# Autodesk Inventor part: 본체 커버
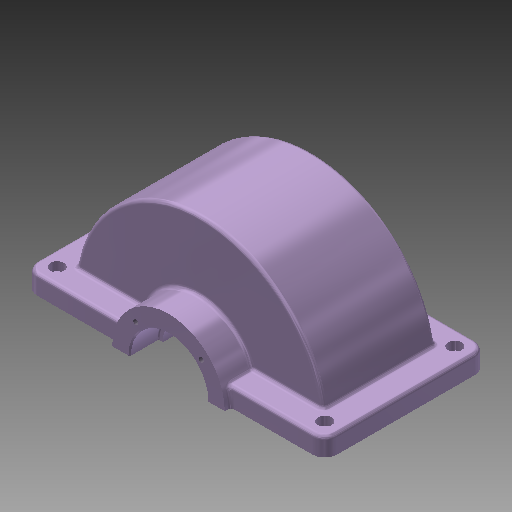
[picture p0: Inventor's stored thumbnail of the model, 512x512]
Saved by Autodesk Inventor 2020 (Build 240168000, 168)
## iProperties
Created: 2023-06
Part Number: 본체 커버
Material: 알루미늄 6061
Document SubType Name: Modeling
Designer: mdu-01
Density: 1 g/cm^3
Appearance: 알루미늄 - 평지(1)
Author: mdu-01
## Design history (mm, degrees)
sketch "스케치1"
  geometry: L1 (0, 70)-(0, -70); L2 (0, 70)-(45, 70); L3 (45, 70)-(45, 45); L4 (45, 45)-(100, 45); L5 (0, 0)-(100, 0); L6 (0, -70)-(45, -70); L7 (45, -70)-(45, -45); L8 (45, -45)-(100, -45); L9 (100, 45)-(100, -45); 1 further point
  constraints: 18 end point, 3 perpendicular, 3 symmetric about line, 2 midpoint, 2 parallel, 1 coincident, 1 vertical
  dimensions: "d0" = 140 distance of L1.start L1.end; "d1" = 90 diameter of L3 L1; "d2" = 90 distance between parallel lines of L8 L4; "d3" = 200 diameter of L9 L1
revolve "회전1" sketch "스케치1" stored, may be unused: angle "d4" = 180 deg
sketch "스케치2"
  geometry: L1 (-10, -110)-(210, -110); L2 (220, -100)-(220, 10); L3 (210, 20)-(-10, 20); L4 (-20, 10)-(-20, -100); L5 (-20, -110)-(220, 20); L6 (220, -110)-(-20, 20); A1 r 10 centre (-10, 10) between (-10, 20) and (-20, 10); A2 r 10 centre (210, 10) between (220, 10) and (210, 20); A3 r 10 centre (210, -100) between (210, -110) and (220, -100); A4 r 10 centre (-10, -100) between (-20, -100) and (-10, -110); 1 further point
  constraints: 12 end point, 8 point on circle, 8 point on line, 8 tangent, 4 centre point, 3 equal radius, 2 midpoint, 2 parallel, 1 horizontal, 1 perpendicular
  dimensions: "d5" = 240 distance of L6.end L5.end; "d6" = 130 distance of L5.end L6.start; "d7" = 10 radius of A1
extrude "돌출1" join sketch "스케치2" distance "d8" = 15; taper "d9" = 0 deg
sketch "스케치3"
  geometry: L1 (0, 70)-(45, 70) reference; L2 (0, -70)-(45, -70) reference; L3 (0, 70)-(0, -70); L4 (31, 70)-(31, 48); L5 (30, 47)-(27.5, 47); L6 (27.5, 47)-(27.5, 32); L7 (27.5, 32)-(87, 32); L8 (0, 0)-(92.097, 0); L9 (31, -70)-(31, -48); L10 (30, -47)-(27.5, -47); L11 (27.5, -47)-(27.5, -32); L12 (27.5, -32)-(87, -32); L13 (87, 32)-(87, -32); L14 (0, 70)-(31, 70); L15 (0, -70)-(31, -70); A1 r 1 centre (30, 48) between (30, 47) and (31, 48); A2 r 1 centre (30, -48) between (31, -48) and (30, -47); 2 further points
  constraints: 26 end point, 5 point on line, 5 symmetric about line, 4 parallel, 4 point on circle, 4 tangent, 3 perpendicular, 2 centre point, 2 collinear, 1 equal radius
  dimensions: "d10" = 1 radius of A1; "d11" = 62 diameter of L4 L3; "d12" = 23 distance between parallel lines of L1 L5; "d13" = 64 distance between parallel lines of L12 L7; "d14" = 55 diameter of L6 L3; "d15" = 87 distance between parallel lines of L13 L3
revolve "회전2" sketch "스케치3" stored, may be unused: angle "d16" = 180 deg
fillet "모깎기1" dims "d17" = 3
fillet "모깎기2" dims "d18" = 3
sketch "스케치4"
  geometry: L1 (-7, -7)-(207, -7); L2 (207, -7)-(207, 97); L3 (207, 97)-(-7, 97); L4 (-7, 97)-(-7, -7); L5 (-7, -7)-(207, 97); L6 (207, -7)-(-7, 97); 1 further point
  constraints: 12 end point, 2 midpoint, 2 parallel, 1 horizontal, 1 perpendicular
  dimensions: "d19" = 214 distance of L3.end L2.end; "d20" = 104 distance of L2.end L1.end
hole "구멍1" sketch "스케치4" at (207, -7), (-7, -7), (207, 97), (-7, 97) diameter "d21" = 6.6; stored, may be unused: countersink angle "d25" = 90 deg, drill point angle "d27" = 118 deg; dims "d22" = 6, "d23" = 11, "d24" = 6.8, "d26" = 8
sketch "스케치5"
  geometry: L1 (-26.163, 26.163)-(26.163, 26.163); L2 (26.163, 26.163)-(26.163, -26.163); L3 (26.163, -26.163)-(-26.163, -26.163); L4 (-26.163, -26.163)-(-26.163, 26.163); A1 r 37 centre (0, 0) between (-26.163, 26.163) and (26.163, -26.163); 1 further point
  constraints: 8 end point, 3 point on circle, 2 parallel, 2 perpendicular, 1 centre point, 1 coincident, 1 horizontal
  dimensions: "d28" = 74 diameter of A1
hole "구멍2" sketch "스케치5" at (-26.163, 26.163), (26.163, 26.163) diameter "d29" = 4.134; stored, may be unused: countersink angle "d33" = 90 deg, drill point angle "d35" = 118 deg; dims "d30" = 10, "d31" = 11, "d32" = 6.8, "d34" = 12
chamfer "모따기1" distance "d36" = 1; stored, may be unused: second distance "d37" = 2, angle "d38" = 45 deg
node "솔리드1"
mirror "대칭1"
